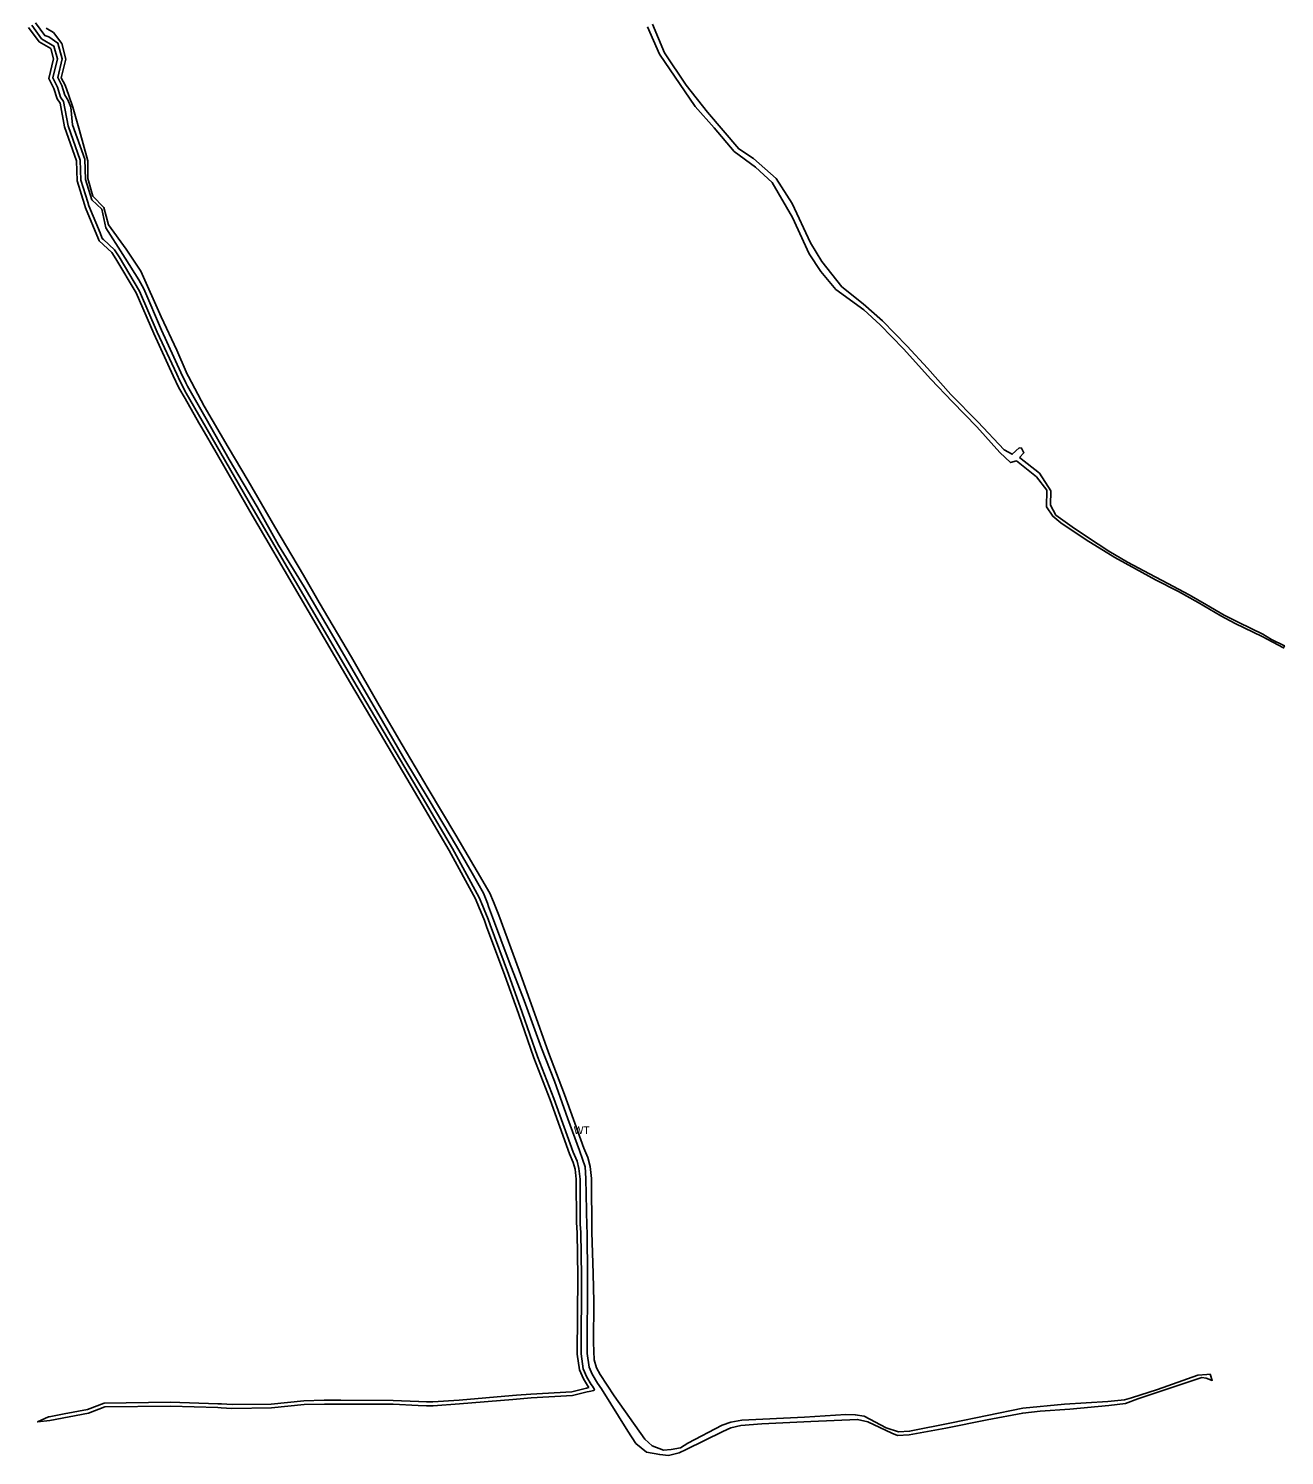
# Model space of a CAD drawing. Extents: x -521621 to -516769, y -1190068 to -1185078.
# Drawn here: x -519671 to -518028, y -1190068 to -1188202 of the extents above; entities that cross this region are included whole.
import ezdxf

# ---------------------------------------------------------------- set-up
doc = ezdxf.new("R2010")
doc.units = 0
for name, color, linetype in [('v_infrastr_n', 7, 'Continuous'), ('v_infrastr_s', 7, 'Continuous'), ('voda_s', 7, 'Continuous')]:
    doc.layers.add(name, color=color, linetype=linetype)

msp = doc.modelspace()

# ---------------------------------------------------------------- linework, layer by layer
at = {"layer": 'v_infrastr_n'}
for points in [[(-519474.1, -1188671.9), (-519481.2, -1188656.2), (-519506.8, -1188600.9), (-519529.8, -1188547.6), (-519556.5, -1188503.2), (-519561.8, -1188494.7), (-519578, -1188479.5), (-519579.2, -1188477.4), (-519595.9, -1188436.5), (-519597.4, -1188431.8), (-519607, -1188400.9), (-519608, -1188374.8), (-519623.6, -1188330.6), (-519629.4, -1188299.4), (-519633.3, -1188293.9), (-519637.3, -1188280.3), (-519644.1, -1188267.2), (-519637.8, -1188241.5), (-519641.6, -1188228.1), (-519656.9, -1188219.1), (-519670.6, -1188200.3)], [(-519666.4, -1188197.6), (-519653.5, -1188215.3), (-519637.4, -1188224.8), (-519632.6, -1188241.5), (-519638.8, -1188266.5), (-519632.7, -1188278.5), (-519628.8, -1188291.7), (-519624.7, -1188297.4), (-519618.8, -1188329.3), (-519603, -1188373.9), (-519602, -1188400.1), (-519593, -1188429.1), (-519591.7, -1188433.7), (-519577.1, -1188468.9), (-519574.1, -1188476.3), (-519572.6, -1188477.7), (-519558, -1188491.5), (-519552.2, -1188500.6), (-519525.3, -1188545.3), (-519502.3, -1188598.8), (-519476.6, -1188654.1), (-519472.8, -1188662.7)], [(-519465.9, -1188685.9), (-519474.1, -1188671.9)], [(-519472.8, -1188662.7), (-519464.3, -1188678.6)], [(-519464.3, -1188678.6), (-519443.4, -1188715.1), (-519376.8, -1188830.4), (-519245, -1189055.5), (-519151.5, -1189214.4), (-519116, -1189274.6), (-519080.9, -1189338.7)], [(-519085.8, -1189340.2), (-519120.4, -1189277.1), (-519155.8, -1189217), (-519215.9, -1189114.9), (-519249.3, -1189058), (-519381.1, -1188833), (-519398.3, -1188803.3), (-519425.3, -1188756.4), (-519444, -1188724), (-519447.7, -1188717.6), (-519465.9, -1188685.9)], [(-518953.8, -1189763.8), (-518954.1, -1189707.2), (-518955.5, -1189694.1), (-518957.9, -1189685.1), (-518962.8, -1189673.7), (-518988, -1189603.3), (-519009.4, -1189548.3), (-519029.7, -1189490.5), (-519047.5, -1189440.7), (-519071.3, -1189376.3), (-519074.1, -1189368.8), (-519079.3, -1189356), (-519080.9, -1189352), (-519085.8, -1189340.2)], [(-519080.9, -1189338.7), (-519076.3, -1189350.1), (-519074.7, -1189354.1), (-519069.4, -1189367), (-519066.6, -1189374.5), (-519042.8, -1189439), (-519025, -1189488.9), (-519004.7, -1189546.6), (-518983.4, -1189601.6), (-518958.1, -1189671.9), (-518953.1, -1189683.5), (-518950.6, -1189693.2), (-518949.1, -1189707), (-518948.8, -1189765.7)], [(-518952.2, -1189834), (-518953, -1189777.1), (-518953.8, -1189763.8)], [(-518948.8, -1189765.7), (-518948, -1189776.9)], [(-518948, -1189776.9), (-518947.2, -1189834), (-518947.8, -1189935.6), (-518945, -1189955.1), (-518940.3, -1189966), (-518934.4, -1189975.6)], [(-518939.5, -1189976.9), (-518944.8, -1189968.3), (-518949.8, -1189956.5), (-518952.8, -1189935.9), (-518952.2, -1189834)], [(-519032.4, -1189989.7), (-519013.4, -1189988.1), (-518959.9, -1189985.1), (-518940.8, -1189980.3), (-518937.8, -1189979.7)], [(-518939.7, -1189985.2), (-518959.1, -1189990.1), (-519013.1, -1189993.1), (-519032.2, -1189994.7)], [(-518937.4, -1189984.8), (-518939.7, -1189985.2)], [(-518937.8, -1189979.7), (-518939.5, -1189976.9)], [(-518934.4, -1189975.6), (-518933, -1189978), (-518930.3, -1189982), (-518931.1, -1189983.5), (-518937.4, -1189984.8)], [(-519032.2, -1189994.7), (-519037.2, -1189995.2), (-519106.8, -1190001), (-519141.4, -1190003.5), (-519150.2, -1190003.5), (-519160.7, -1190003), (-519193.8, -1190001.4), (-519262.1, -1190001.2), (-519283.6, -1190001.2), (-519310, -1190002), (-519352.8, -1190006.3), (-519404.5, -1190006.9), (-519418.5, -1190006.1), (-519423, -1190005.8), (-519484.8, -1190003.9), (-519570.6, -1190005), (-519592.2, -1190013.2), (-519642.9, -1190022.7), (-519658.8, -1190024.5), (-519644.5, -1190017.9), (-519643.6, -1190017.8), (-519624, -1190014.1), (-519593.6, -1190008.4), (-519571.6, -1190000), (-519484.8, -1189998.9), (-519422.8, -1190000.8), (-519418.2, -1190001.1), (-519404.3, -1190001.9), (-519353, -1190001.3), (-519310.3, -1189997), (-519283.7, -1189996.2), (-519262.1, -1189996.2), (-519193.6, -1189996.5), (-519160.5, -1189998), (-519160.2, -1189998), (-519150, -1189998.5), (-519141.6, -1189998.5), (-519107.2, -1189996.1), (-519037.4, -1189990.2)], [(-519037.4, -1189990.2), (-519032.4, -1189989.7)]]:
    msp.add_lwpolyline(points, dxfattribs=at)
at = {"layer": 'v_infrastr_s'}
for points in [[(-518860.7, -1188199.6), (-518845.2, -1188235.2), (-518798.3, -1188303.9), (-518773.6, -1188331.7), (-518747.4, -1188362.8), (-518719.5, -1188383.2), (-518698, -1188403.1), (-518671.2, -1188448.9), (-518649.2, -1188496.5), (-518634, -1188519.5), (-518614.4, -1188543.2), (-518577.8, -1188569.8), (-518556.3, -1188589.4), (-518526.1, -1188620.6), (-518490.3, -1188660.4), (-518462, -1188690.2), (-518430.1, -1188722.7), (-518399.9, -1188756.4), (-518386, -1188769.6), (-518378.1, -1188767.2)], [(-518374.4, -1188763), (-518368.5, -1188756.8), (-518371.5, -1188750.7), (-518374.5, -1188750.3), (-518383.7, -1188758.8), (-518394.5, -1188752.8), (-518428.7, -1188716.1), (-518463.9, -1188680.7), (-518494.6, -1188646.3), (-518521.3, -1188617.2), (-518553.6, -1188584.3), (-518578.9, -1188561.9), (-518606.8, -1188539.5), (-518633, -1188506.5), (-518647.5, -1188482.3), (-518671.6, -1188430.9), (-518692.6, -1188397.9), (-518722.2, -1188371.9), (-518741.4, -1188359.3), (-518782.4, -1188311.1), (-518810.5, -1188276.1), (-518838.6, -1188233.7), (-518854.5, -1188196.2)], [(-518378.1, -1188767.2), (-518352, -1188788.2), (-518338.5, -1188805.8), (-518338.7, -1188827.4), (-518330.5, -1188839.9), (-518320.2, -1188848.3), (-518287.1, -1188870.6), (-518249.3, -1188893.8), (-518222.5, -1188908.4), (-518196.1, -1188922.9), (-518166.2, -1188938.4), (-518140.7, -1188952.5), (-518110.8, -1188970.3), (-518091.9, -1188980.1), (-518056.6, -1188997), (-518028.7, -1189012), (-518027.6, -1189009.2), (-518044.4, -1189001.2), (-518055.8, -1188993.9), (-518087.5, -1188979), (-518106.5, -1188969.1), (-518129.5, -1188955.6), (-518152.1, -1188942.6), (-518180, -1188927.7), (-518204.1, -1188915.2), (-518232.9, -1188899.8), (-518257.4, -1188885.6), (-518271.3, -1188876.5), (-518302.4, -1188855.7), (-518326.9, -1188838.2), (-518333.7, -1188825.5), (-518333.1, -1188806.7), (-518348.2, -1188783.4), (-518374.4, -1188763)]]:
    msp.add_lwpolyline(points, dxfattribs=at)
at = {"layer": 'voda_s'}
msp.add_lwpolyline([(-519661.3, -1188194.4), (-519649.4, -1188210.8), (-519644.1, -1188212.8), (-519632.2, -1188220.8), (-519626.4, -1188241.3), (-519632.4, -1188265.8), (-519627.1, -1188276.2), (-519623.3, -1188289), (-519619.1, -1188295), (-519615.4, -1188304.7), (-519613, -1188327.8), (-519597.1, -1188372.8), (-519596.1, -1188399.1), (-519587.7, -1188425.8), (-519574.7, -1188438.3), (-519569.3, -1188462.3), (-519547.1, -1188497.4), (-519544, -1188502.3), (-519526.3, -1188530.5), (-519519.9, -1188542.5), (-519496.8, -1188596.4), (-519471.2, -1188651.7), (-519464.9, -1188665.5), (-519462.5, -1188669.8), (-519438.2, -1188712.2), (-519408.1, -1188765.7), (-519371.6, -1188827.4), (-519343.5, -1188877.7), (-519310.2, -1188932.1), (-519271.2, -1188998.6), (-519239.8, -1189052.4), (-519207.6, -1189107.7), (-519179.5, -1189156.4), (-519146.3, -1189211.4), (-519110.8, -1189271.6), (-519090.3, -1189306.6), (-519075.2, -1189333), (-519070.4, -1189346), (-519068.7, -1189350.5), (-519063.6, -1189364.5), (-519042, -1189422.7), (-519022.2, -1189473.1), (-518999.6, -1189535.6), (-518982.7, -1189579), (-518965.3, -1189627.9), (-518950, -1189669.6), (-518945.9, -1189680.7), (-518942.2, -1189690.9), (-518941.7, -1189706.3), (-518940.1, -1189769.1), (-518940, -1189776.8), (-518939.2, -1189833.9), (-518939.8, -1189935), (-518937.2, -1189952.9), (-518933.2, -1189962.3), (-518926.3, -1189973.7), (-518920.9, -1189981.4), (-518886.5, -1190036.6), (-518876.2, -1190052.7), (-518862.2, -1190064.2), (-518844.8, -1190067.3), (-518833.4, -1190068.5), (-518819.6, -1190065), (-518810.3, -1190060.8), (-518762.2, -1190037), (-518752, -1190032.3), (-518738.7, -1190029.2), (-518711.1, -1190027.2), (-518647, -1190024.2), (-518586, -1190021.3), (-518572.8, -1190024.7), (-518557, -1190031.8), (-518541.2, -1190039.5), (-518534, -1190042.5), (-518518.7, -1190041.7), (-518470.5, -1190032.6), (-518416.5, -1190021.7), (-518369.9, -1190013), (-518347.2, -1190010.6), (-518308.3, -1190007.9), (-518257.4, -1190003), (-518235.4, -1190000.4), (-518219.4, -1189994.6), (-518135.5, -1189966.6), (-518130.2, -1189967.2), (-518122, -1189970.3), (-518125, -1189962.2), (-518129.1, -1189962.6), (-518141, -1189963.6), (-518193.8, -1189982.2), (-518227.5, -1189993.1), (-518236.9, -1189995.7), (-518258.7, -1189997.8), (-518315.3, -1190001.3), (-518369.8, -1190006.7), (-518463.3, -1190026), (-518518.1, -1190036.9), (-518532.7, -1190037.7), (-518548.6, -1190032.2), (-518577.5, -1190017.2), (-518589.2, -1190015.2), (-518601.4, -1190014.7), (-518655.6, -1190018.4), (-518737.5, -1190022.4), (-518751.9, -1190025.1), (-518763.1, -1190028.8), (-518807.9, -1190052.2), (-518817.9, -1190058.4), (-518830, -1190060.7), (-518840.1, -1190061.5), (-518854.8, -1190056.1), (-518864.4, -1190047.1), (-518904.5, -1189990.3), (-518922.9, -1189962.6), (-518927.8, -1189953.9), (-518930.7, -1189943.3), (-518931.5, -1189920.7), (-518931.2, -1189867.5), (-518932.1, -1189830.3), (-518933.5, -1189776.3), (-518934.1, -1189706.1), (-518935.8, -1189690.5), (-518938.9, -1189678.6), (-518944.2, -1189666.4), (-518969.3, -1189596.4), (-518990.6, -1189541.4), (-519010.8, -1189483.9), (-519028.7, -1189433.9), (-519055.4, -1189361.6), (-519060.8, -1189348.5), (-519062.4, -1189344.4), (-519067, -1189333.1), (-519083.5, -1189304.4), (-519111.8, -1189257), (-519147.7, -1189196.3), (-519181.7, -1189138.9), (-519211.8, -1189087.2), (-519248.2, -1189024.1), (-519290.2, -1188952.7), (-519310.8, -1188916.9), (-519348.6, -1188853.6), (-519383.4, -1188793.4), (-519409.5, -1188749.6), (-519440.9, -1188695.6), (-519461.3, -1188656.8), (-519463.3, -1188653), (-519464.3, -1188650.7), (-519476.4, -1188622.4), (-519497.1, -1188578.9), (-519523.7, -1188519.3), (-519542.9, -1188490.6), (-519566.1, -1188458.8), (-519572.3, -1188435.8), (-519586.5, -1188421.3), (-519593.1, -1188398), (-519593.1, -1188374.9), (-519603.9, -1188335.4), (-519612.5, -1188304.7), (-519617.9, -1188289.5), (-519622.6, -1188276.1), (-519627.8, -1188266.2), (-519621.8, -1188241.7), (-519626.9, -1188221.5), (-519638, -1188207.1), (-519647.4, -1188201.3)], dxfattribs=at)

# ---------------------------------------------------------------- texts
msp.add_text('WT', height=10, dxfattribs=at).set_placement((-518957.3, -1189648))

doc.saveas('drawing.dxf')
